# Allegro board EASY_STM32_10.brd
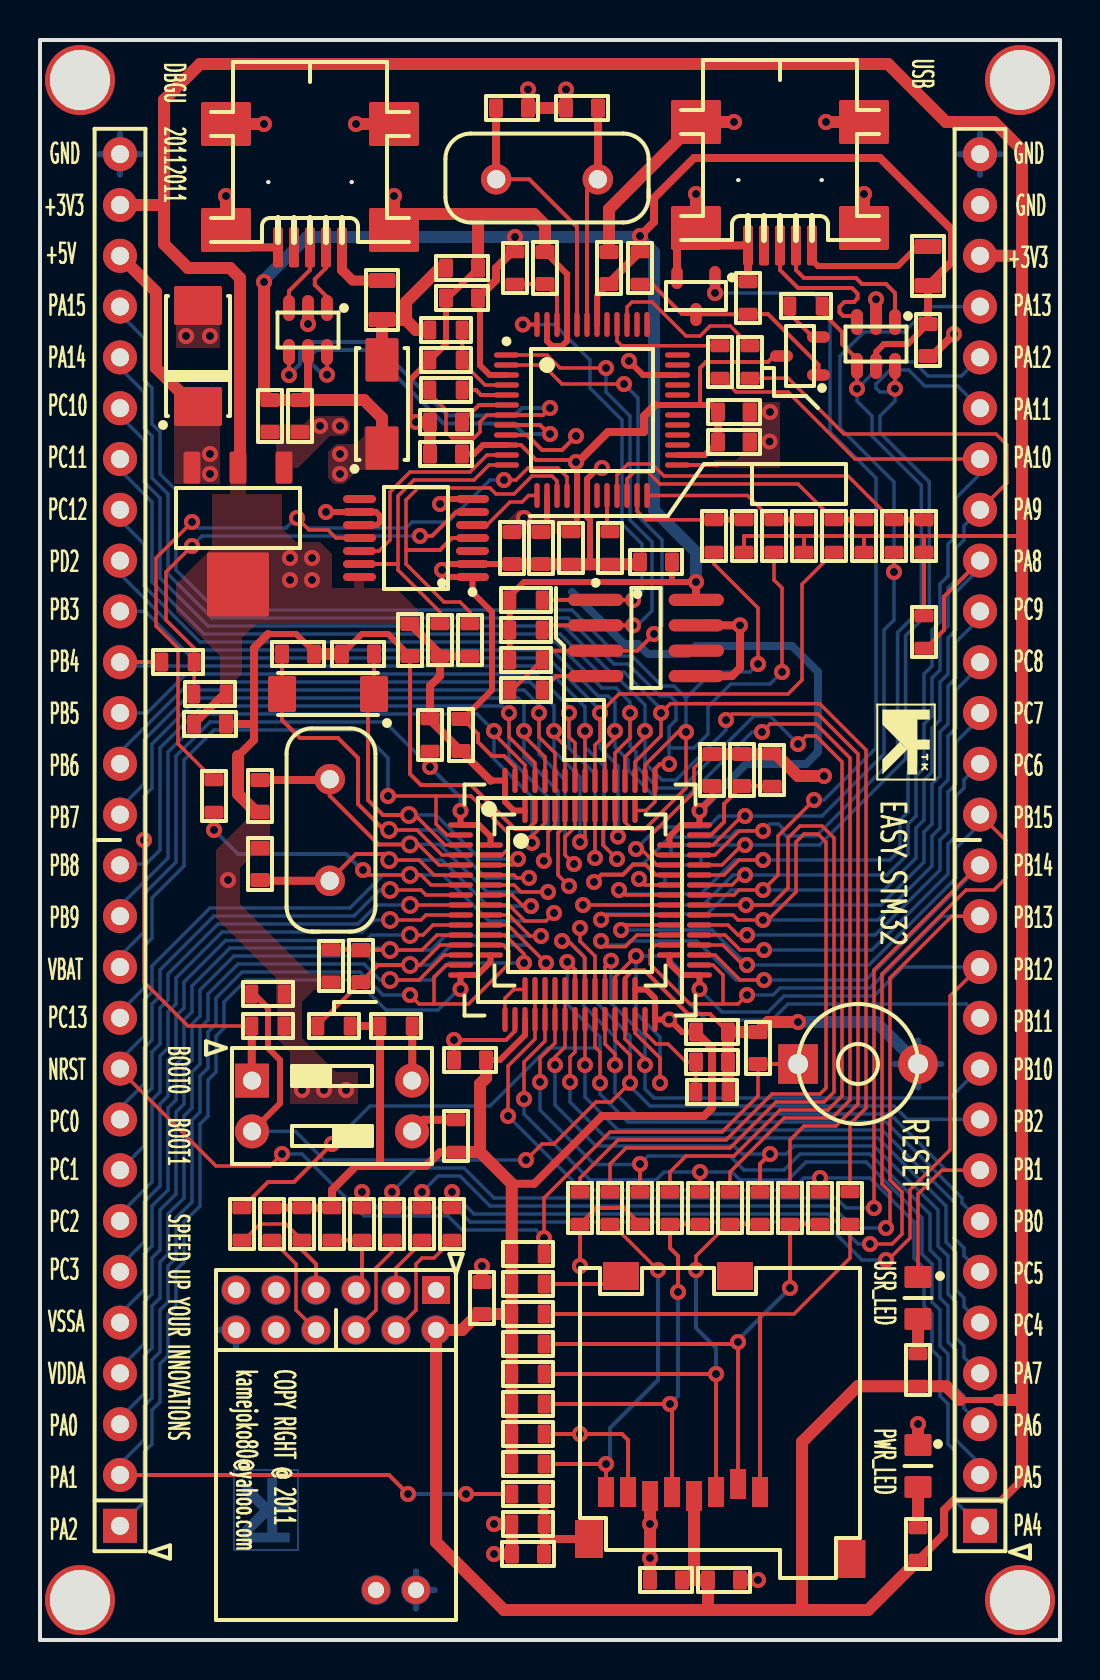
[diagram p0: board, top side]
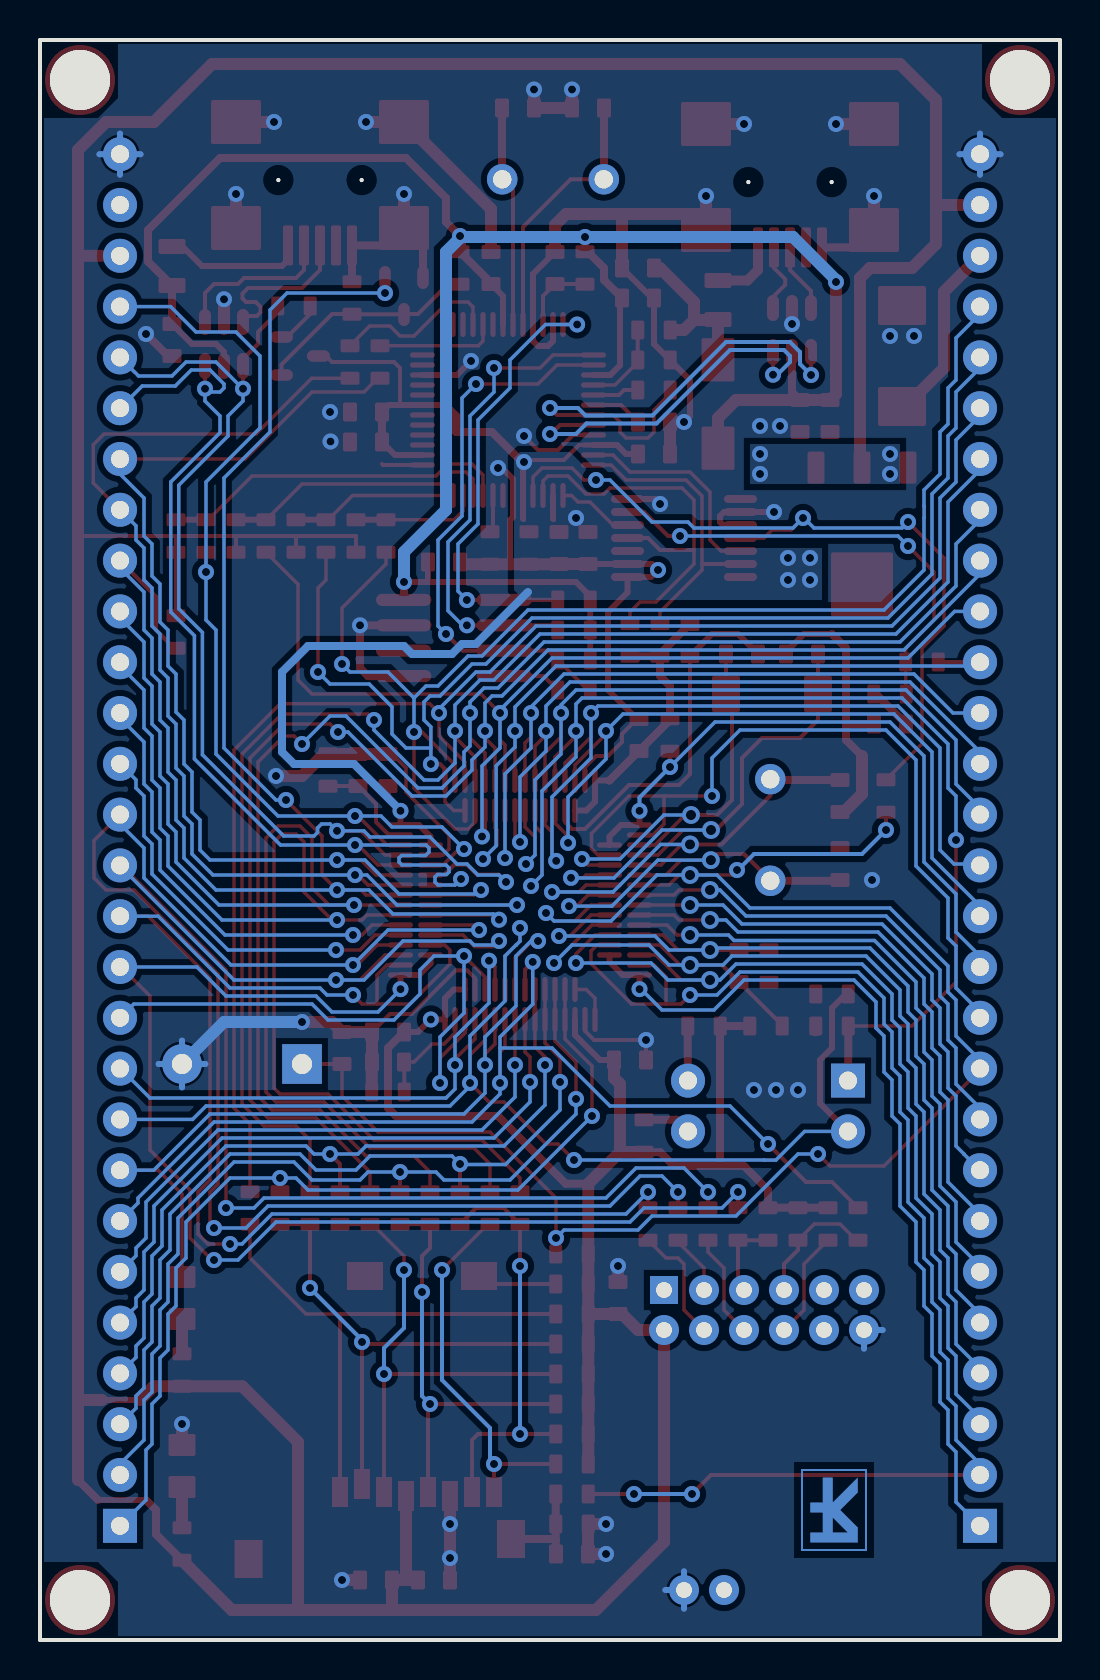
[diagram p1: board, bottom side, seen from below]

Outline 51 x 80 mm; copper layers: TOP, BOTTOM. Coordinates in mm from the lower left corner of the outline.
Outline path: 0,80 0,0 51,0 51,80 0,80

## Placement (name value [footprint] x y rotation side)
C1  22p  [CAP0603_B]  11 42.2 270 top
C2  22p  [CAP0603_B]  11 38.8 90 top
C3  15p  [CAP0603_B]  12.9 49.3 0 top
C4  15p  [CAP0603_B]  15.9 49.3 180 top
C5  100n  [CAP0603_B]  16.05 33.7 90 top
C6  100n  [CAP0603_B]  33.6 30.4 0 top
C7  100n  [CAP0603_B]  33.6 43.5 90 top
C8  100n  [CAP0603_B]  21.05 45.25 90 top
C9  100n  [CAP0603_B]  21.5 29 180 top
C10  10u  [CAP0603_B]  21.1 68.6 0 top
C11  100n  [CAP0603_B]  21.1 67.1 180 top
C12  100n  [CAP0603_B]  28.45 68.6 90 top
C13  10u  [CAP0603_B]  23.6 54.6 270 top
C14  100n  [CAP0603_B]  20.3 59.3 180 top
C15  100n  [CAP0603_B]  25.05 54.6 270 top
C16  100n  [CAP0603_B]  34.7 59.9 0 top
C17  100n  [CAP0603_B]  34.7 61.4 0 top
C18  100n  [CAP0603_B]  25.25 68.6 90 top
C19  100n  [CAP0603_B]  20.3 60.9 180 top
C20  22p  [CAP0603_B]  27.1 76.6 180 top
C21  22p  [CAP0603_B]  23.6 76.6 0 top
C22  100n  [CAP0603_B]  30.8 53.9 180 top
C23  220u  [CAP220UF]  7.9 64.2 90 top
C24  100n  [CAP0603_B]  11.5 61.2 270 top
C25  10u  [CAP0603_B]  8.5 45.8 0 top
C26  100n  [CAP0603_B]  44.4 65 270 top
C27  100n  [CAP0603_B]  33.6 28.9 0 top
C28  100n  [CAP0603_B]  35.1 43.5 90 top
C29  100n  [CAP0603_B]  13 61.2 270 top
C43  100n  [CAP0603_B]  31.3 3 180 top
C44  10u  [CAP0603_B]  34.2 3 0 top
C46  100n  [CAP0603_B]  18.5 50 270 top
C47  100n  [CAP0603_B]  24.4 4.3 180 top
C48  100n  [CAP0603_B]  35.9 29.6 90 top
C49  100n  [CAP0603_B]  22.1 17.1 90 top
D1  LED  [LEDC2012X120M]  43.9 8.7 270 top
D2  1N5819  [SS14]  17.1 61.8 90 top
D3  LED  [LEDC2012X120M]  43.9 17.1 270 top
J1  USB_MB  [HIROSE-US60-MB-5ST]  13.5 78.9 180 top
J2  USB_MB  [HIROSE-US60-MB-5ST]  37 79 180 top
J3  CON28  [CON28-1X28]  47 5.71 90 top
J4  CON28  [CON28-1X28]  4 5.71 90 top
L1  FB60R  [RES0805_B]  17.1 67 90 top
L2  FB60R  [RES0805_B]  44.4 68.7 90 top
NOREF  -  []  41.86 46.77 270 top
NOREF#2  val  [unnamed#2]  49 2 0 top
NOREF#3  -  []  0.07 0.66 0 top
NOREF#4  -  []  51.55 -0.02 90 top
NOREF#5  val  [unnamed#2]  2 78 0 top
NOREF#6  val  [unnamed#2]  49 78 0 top
NOREF#7  val  [unnamed#2]  2 2 0 top
NOREF#8  -  []  9.86 4.62 90 bottom
Q1  C1815  [SOT-23]  38 64.2 90 top
Q2  C1815  [SOT-23]  32.8 67.2 180 top
R1  0R  [RES0603_B]  19.5 45.25 90 top
R2  0R  [RES0603_B]  14.7 30.7 0 top
R3  0R  [RES0603_B]  14.55 33.7 270 top
R4  470R  [RES0603_B]  23.75 68.6 270 top
R5  4K7  [RES0603_B]  20.3 65.5 0 top
R6  10K  [RES0603_B]  20.3 64 180 top
R7  10K  [RES0603_B]  28.5 54.6 270 top
R8  10K  [RES0603_B]  24.3 49 0 top
R9  10K  [RES0603_B]  24.3 50.5 0 top
R10  10K  [RES0603_B]  24.3 52 0 top
R11  2K2  [RES0603_B]  24.3 47.5 0 top
R12  330R  [RES0603_B]  43.9 4.8 90 top
R13  1K5  [RES0603_B]  20.3 62.5 0 top
R14  100K  [RES0603_B]  26.55 54.6 270 top
R15  10K  [RES0603_B]  24.4 10.3 0 top
R16  10K  [RES0603_B]  24.4 13.3 0 top
R17  10K  [RES0603_B]  24.4 11.8 0 top
R18  10K  [RES0603_B]  24.4 14.8 0 top
R19  10K  [RES0603_B]  24.4 8.8 0 top
R20  10K  [RES0603_B]  24.4 16.3 0 top
R21  10K  [RES0603_B]  24.4 17.8 0 top
R22  1K  [RES0603_B]  24.4 5.8 180 top
R23  0R  [RES0603_B]  27 21.6 270 top
R24  0R  [RES0603_B]  34.5 21.6 270 top
R25  0R  [RES0603_B]  31.5 21.6 270 top
R26  0R  [RES0603_B]  37.5 21.6 270 top
R27  0R  [RES0603_B]  28.5 21.6 270 top
R28  0R  [RES0603_B]  40.5 21.6 270 top
R29  0R (DNP)  [RES0603_B]  30 21.6 90 top
R30  0R (DNP)  [RES0603_B]  36 21.6 90 top
R31  0R (DNP)  [RES0603_B]  33 21.6 90 top
R32  0R (DNP)  [RES0603_B]  39 21.6 90 top
R33  0R  [RES0603_B]  24.4 7.3 0 top
R34  39R  [RES0603_B]  34 63.9 270 top
R35  100R  [RES0603_B]  39.7 55.2 270 top
R36  100R  [RES0603_B]  42.7 55.2 270 top
R37  100R  [RES0603_B]  33.7 55.2 270 top
R38  100R  [RES0603_B]  36.7 55.2 270 top
R39  100K  [RES0603_B]  20 50 90 top
R40  100K  [RES0603_B]  21.5 50 90 top
R41  100R  [RES0603_B]  6.9 48.9 180 top
R42  100R  [RES0603_B]  8.7 42.2 270 top
R43  0R  [RES0603_B]  33.6 27.4 0 top
R44  10K  [RES0603_B]  30 68.6 270 top
R45  36K  [RES0603_B]  35.4 67.1 90 top
R46  1K5  [RES0603_B]  38.3 66.7 0 top
R47  47K  [RES0603_B]  44.2 50.4 270 top
R48  0R  [RES0603_B]  36.6 43.5 90 top
R49  10K  [RES0603_B]  24.4 19.3 0 top
R50  1K  [RES0603_B]  11.4 30.7 0 top
R51  1K  [RES0603_B]  11.4 32.3 0 top
R52  10K  [RES0603_B]  17.8 30.7 0 top
R53  10K  [RES0603_B]  20.8 25.2 90 top
R54  10K  [RES0603_B]  8.5 47.3 180 top
R55  10K  [RES0603_B]  41.2 55.2 90 top
R56  10K  [RES0603_B]  44.2 55.2 90 top
R57  10K  [RES0603_B]  35.2 55.2 90 top
R58  10K  [RES0603_B]  38.2 55.2 90 top
R59  39R  [RES0603_B]  35.5 63.9 270 top
R60  10K  [RES0603_B]  14.6 20.8 270 top
R61  0R  [RES0603_B]  16.1 20.8 270 top
R62  10K  [RES0603_B]  11.6 20.8 270 top
R63  10K  [RES0603_B]  13.1 20.8 270 top
R64  0R  [RES0603_B]  10.1 20.8 270 top
R65  0R  [RES0603_B]  19.1 20.8 270 top
R66  0R  [RES0603_B]  20.6 20.8 90 top
R67  0R  [RES0603_B]  17.6 20.8 90 top
R70  330R  [RES0603_B]  43.9 13.5 90 top
S1  BT  [BUTTON_RST_CIRCLE]  40.9 28.8 0 top
S2  SW DIP-2  [DIP_SWITCH_2]  14.6 26.7 270 top
U1  STM32F103RCT6  [LQFP64_MODIFIED]  27 37 0 top
U2  STM32F100  [LQFP48L_MODIFIED]  27 37 0 top
U3  FT2232D  [LQFP48L]  27.6 61.5 0 top
U4  AT93C46-10SI-2.7  [SOIC8S1JEDECM]  30.3 50.1 270 top
U6  74LVC125A  [TSOP65P640X120-14]  18.8 55.1 90 top
U7  LD1117-3V3  [SOT-223]  9.9 55.42 180 top
U8  RFM12  [RFM12-2X6]  19.8 17.5 180 top
U10  MICRO_SD  [MICRO_SD_PUSH]  41 18.6 180 top
U11  USBLC6-2P6  [SOT23-6L]  41.8 64.8 180 top
U12  USBLC6-2P6  [SOT23-6L]  13.4 65.5 180 top
Y1  8M  [XTAL_DIP]  14.49 37.96 90 top
Y2  32.768KHz  [ABS10]  14.4 47.3 180 top
Y3  6M  [XTAL_DIP]  27.89 73.04 180 top

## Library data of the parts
C1-C9 C24 C25 C27 C28 = C1005_0: User Part Number: pn; Tolerance: RichardLC
C10-C22 C26 C29 = CAP NP_0: User Part Number: pn; Tolerance: RichardLC
C23 = CAPACITOR POL: User Part Number: pn; Tolerance: RichardLC
C43 C44 C46-C49 = C1005_5: User Part Number: pn; Tolerance: RichardLC
D1 D3 = LED_0: User Part Number: pn; Tolerance: RichardLC
D2 = DIODE SCHOTTKY_1: User Part Number: pn; Tolerance: RichardLC
J1 J2 = CON9_2: User Part Number: pn; Tolerance: RichardLC
J3 J4 = CON26_0: User Part Number: pn; Tolerance: RichardLC
L1 L2 = INDUCTOR/SM_0: User Part Number: pn; Tolerance: RichardLC
NOREF#2 NOREF#6 NOREF#7 = -: User Part Number: pn; Tolerance: RichardLC
NOREF#5 = -: Tolerance: RichardLC; User Part Number: pn
Q1 Q2 = 2N3904_0: User Part Number: pn; Tolerance: RichardLC
R1-R67 R70 = R_0: User Part Number: pn; Tolerance: RichardLC
S1 = SW PUSHBUTTON_1: User Part Number: pn; Tolerance: RichardLC
S2 = SW DIP-2_1: User Part Number: pn; Tolerance: RichardLC
U1 = STM32F103RCT6_2: User Part Number: pn; Tolerance: RichardLC
U2 = STM32F100_1: User Part Number: pn; Tolerance: RichardLC
U3 = FT2232D_0: User Part Number: pn; Tolerance: RichardLC
U4 = 93C46_2: User Part Number: pn; Tolerance: RichardLC
U6 = 74HC125/LCC_0: User Part Number: pn; Tolerance: RichardLC
U7 = LD1117: User Part Number: pn; Tolerance: RichardLC
U8 = RFM12: User Part Number: pn; Tolerance: RichardLC
U10 = MOLEX_uSD_0: User Part Number: pn; Tolerance: RichardLC
U11 U12 = USBLC6-2P6: User Part Number: pn; Tolerance: RichardLC
Y1 Y3 = ZTB: Tolerance: ***; User Part Number: ***
Y2 = ZTA: User Part Number: pn; Tolerance: RichardLC

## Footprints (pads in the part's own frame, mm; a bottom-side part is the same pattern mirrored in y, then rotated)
ABS10
  custom 0.35x0.35 smd: 1(-2.3,0) 2(2.3,0)
BUTTON_RST_CIRCLE
  rect 1.98x1.98 hole 1: 1(-3,0)
  round 1.98 hole 1: 2(3,0)
CAP220UF
  custom 0.487x0.487 smd: 1(-2.525,0) 2(2.525,0)
CAP0603_B
  custom 0.175x0.175 smd: 1(-0.8,0) 2(0.8,0)
CON28-1X28
  rect 1.7x1.7 hole 0.9: 1(0,0)
  round 1.7 hole 0.9: 2(2.54,0) 3(5.08,0) 4(7.62,0) 5(10.16,0) 6(12.7,0) 7(15.24,0) 8(17.78,0) 9(20.32,0) 10(22.86,0) 11(25.4,0) 12(27.94,0) 13(30.48,0) 14(33.02,0) 15(35.56,0) 16(38.1,0) 17(40.64,0) 18(43.18,0) 19(45.72,0) 20(48.26,0) 21(50.8,0) 22(53.34,0) 23(55.88,0) 24(58.42,0) 25(60.96,0) 26(63.5,0) 27(66.04,0) 28(68.58,0)
DIP_SWITCH_2
  rect 1.7x1.7 hole 0.9: 1(-1.27,-4)
  round 1.7 hole 0.9: 2(1.27,-4) 3(1.27,4) 4(-1.27,4)
HIROSE-US60-MB-5ST
  round 0.2 hole 0.9 unplated: (-2.083,6.005) (2.083,6.005)
  custom 0.125x0.125 smd: 1(-1.6,9.271) 2(-0.8,9.271) 3(0,9.271) 4(0.8,9.271) 5(1.6,9.271)
  custom 0.55x0.55 smd: 6(-4.2,3.1) 7(4.2,3.1) 8(-4.2,8.4) 9(4.2,8.4)
LEDC2012X120M
  custom 0.275x0.275 smd: A(1.05,0) C(-1.05,0)
LQFP48L
  oval 1.25x0.27 smd: 1(-4.275,2.75) 2(-4.275,2.25) 3(-4.275,1.75) 4(-4.275,1.25) 5(-4.275,0.75) 6(-4.275,0.25) 7(-4.275,-0.25) 8(-4.275,-0.75) 9(-4.275,-1.25) 10(-4.275,-1.75) 11(-4.275,-2.25) 12(-4.275,-2.75) 25(4.275,-2.75) 26(4.275,-2.25) 27(4.275,-1.75) 28(4.275,-1.25) 29(4.275,-0.75) 30(4.275,-0.25) 31(4.275,0.25) 32(4.275,0.75) 33(4.275,1.25) 34(4.275,1.75) 35(4.275,2.25) 36(4.275,2.75)
  oval 0.27x1.25 smd: 13(-2.75,-4.275) 14(-2.25,-4.275) 15(-1.75,-4.275) 16(-1.25,-4.275) 17(-0.75,-4.275) 18(-0.25,-4.275) 19(0.25,-4.275) 20(0.75,-4.275) 21(1.25,-4.275) 22(1.75,-4.275) 23(2.25,-4.275) 24(2.75,-4.275) 37(2.75,4.275) 38(2.25,4.275) 39(1.75,4.275) 40(1.25,4.275) 41(0.75,4.275) 42(0.25,4.275) 43(-0.25,4.275) 44(-0.75,4.275) 45(-1.25,4.275) 46(-1.75,4.275) 47(-2.25,4.275) 48(-2.75,4.275)
LQFP48L_MODIFIED
  oval 1.25x0.27 smd: 1(-4.475,2.75) 2(-4.475,2.25) 3(-4.475,1.75) 4(-4.475,1.25) 5(-4.475,0.75) 6(-4.475,0.25) 7(-4.475,-0.25) 8(-4.475,-0.75) 9(-4.475,-1.25) 10(-4.475,-1.75) 11(-4.475,-2.25) 12(-4.475,-2.75) 25(4.475,-2.75) 26(4.475,-2.25) 27(4.475,-1.75) 28(4.475,-1.25) 29(4.475,-0.75) 30(4.475,-0.25) 31(4.475,0.25) 32(4.475,0.75) 33(4.475,1.25) 34(4.475,1.75) 35(4.475,2.25) 36(4.475,2.75)
  oval 0.27x1.25 smd: 13(-2.75,-4.475) 14(-2.25,-4.475) 15(-1.75,-4.475) 16(-1.25,-4.475) 17(-0.75,-4.475) 18(-0.25,-4.475) 19(0.25,-4.475) 20(0.75,-4.475) 21(1.25,-4.475) 22(1.75,-4.475) 23(2.25,-4.475) 24(2.75,-4.475) 37(2.75,4.475) 38(2.25,4.475) 39(1.75,4.475) 40(1.25,4.475) 41(0.75,4.475) 42(0.25,4.475) 43(-0.25,4.475) 44(-0.75,4.475) 45(-1.25,4.475) 46(-1.75,4.475) 47(-2.25,4.475) 48(-2.75,4.475)
LQFP64_MODIFIED
  oval 1.25x0.27 smd: 1(-5.975,3.75) 2(-5.975,3.25) 3(-5.975,2.75) 4(-5.975,2.25) 5(-5.975,1.75) 6(-5.975,1.25) 7(-5.975,0.75) 8(-5.975,0.25) 9(-5.975,-0.25) 10(-5.975,-0.75) 11(-5.975,-1.25) 12(-5.975,-1.75) 13(-5.975,-2.25) 14(-5.975,-2.75) 15(-5.975,-3.25) 16(-5.975,-3.75) 33(5.975,-3.75) 34(5.975,-3.25) 35(5.975,-2.75) 36(5.975,-2.25) 37(5.975,-1.75) 38(5.975,-1.25) 39(5.975,-0.75) 40(5.975,-0.25) 41(5.975,0.25) 42(5.975,0.75) 43(5.975,1.25) 44(5.975,1.75) 45(5.975,2.25) 46(5.975,2.75) 47(5.975,3.25) 48(5.975,3.75)
  oval 0.27x1.25 smd: 17(-3.75,-5.975) 18(-3.25,-5.975) 19(-2.75,-5.975) 20(-2.25,-5.975) 21(-1.75,-5.975) 22(-1.25,-5.975) 23(-0.75,-5.975) 24(-0.25,-5.975) 25(0.25,-5.975) 26(0.75,-5.975) 27(1.25,-5.975) 28(1.75,-5.975) 29(2.25,-5.975) 30(2.75,-5.975) 31(3.25,-5.975) 32(3.75,-5.975) 49(3.75,5.975) 50(3.25,5.975) 51(2.75,5.975) 52(2.25,5.975) 53(1.75,5.975) 54(1.25,5.975) 55(0.75,5.975) 56(0.25,5.975) 57(-0.25,5.975) 58(-0.75,5.975) 59(-1.25,5.975) 60(-1.75,5.975) 61(-2.25,5.975) 62(-2.75,5.975) 63(-3.25,5.975) 64(-3.75,5.975)
MICRO_SD_PUSH
  rect 0.8x1.5 smd: 1(5,11.2) 2(6.1,10.8) 3(7.2,11.2) 4(8.3,11.4) 5(9.4,11.2) 6(10.5,11.4) 7(11.6,11.2) 8(12.7,11.2)
  rect 1.4x1.9 smd: G1(0.43,14.55) G2(13.55,13.55)
  rect 1.8x1.4 smd: S1(6.25,0.4) S2(11.95,0.4)
RES0603_B
  custom 0.163x0.163 smd: 1(-0.812,0) 2(0.812,0)
RES0805_B
  custom 0.188x0.188 smd: 1(-0.975,0) 2(0.975,0)
RFM12-2X6
  rect 1.4x1.4 hole 0.8: 1(0,0)
  round 1.4 hole 0.8: 2(0,2) 3(2,0) 4(2,2) 5(4,0) 6(4,2) 7(6,0) 8(6,2) 9(8,0) 10(8,2) 11(10,0) 12(10,2) 13(1,15) 14(3,15)
SOIC8S1JEDECM
  oval 0.61x2.77 smd: 1(-1.905,-2.515) 2(-0.635,-2.515) 3(0.635,-2.515) 4(1.905,-2.515) 5(1.905,2.515) 6(0.635,2.515) 7(-0.635,2.515) 8(-1.905,2.515)
SOT23-6L
  oval 0.6x1.3 smd: 1(-0.95,-1.1) 2(0,-1.1) 3(0.95,-1.1) 4(0.95,1.1) 5(0,1.1) 6(-0.95,1.1)
SOT-23
  oval 0.58x1.15 smd: 1(-0.95,-0.925) 2(0.95,-0.925) 3(0,0.925)
SOT-223
  custom 0.21x0.21 smd: 1(-2.3,-3.195) 2(0,-3.195) 3(2.3,-3.195)
  custom 0.775x0.775 smd: 4(0,2.645)
SS14
  custom 0.412x0.412 smd: A(2.21,0) C(-2.21,0)
TSOP65P640X120-14
  oval 0.4x1.65 smd: 1(-1.95,-2.825) 2(-1.3,-2.825) 3(-0.65,-2.825) 4(0,-2.825) 5(0.65,-2.825) 6(1.3,-2.825) 7(1.95,-2.825) 8(1.95,2.825) 9(1.3,2.825) 10(0.65,2.825) 11(0,2.825) 12(-0.65,2.825) 13(-1.3,2.825) 14(-1.95,2.825)
unnamed#2
  round 3.5 hole 3: 1(0,0)
XTAL_DIP
  round 1.524 hole 0.914: 1(0,0) 2(5.08,0)

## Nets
+3V3: C6.1 C7.1 C8.1 C9.1 C13.1 C14.1 C15.1 C16.1 C17.1 C25.1 C43.1 C44.1 C46.1 C49.1 J3.26 J4.27 Q1.3(C) R1.2 R2.2 R12.1 R14.1 R15.1 R16.1 R17.1 R18.1 R19.1 R20.1 R21.1 R39.1 R40.1 R47.1 R49.1 R52.1 R53.1 R54.1 R55.1 R56.1 R57.1 R58.1 R60.1 R62.1 R63.1 R70.1 U1.19(VDD_4) U1.32(VDD_1) U1.48(VDD_2) U1.64(VDD_3) U2.24(VDD_1) U2.36(VDD_2) U2.48(VDD_3) U3.10(SI/WUA) U3.14(VCCIOA) U3.17(ADBUS6) U3.26(SI/WUB) U3.31(VCCIOB) U6.14(VCC) U7.2(VOUT) U7.4(SH) U8.2(VDD) U10.4(VDD)
+5V: C11.1 C12.1 C22.1 C23.1 C24.1 C26.1 C29.1 D2.C J4.26 L2.1 R4.1 R8.1 R9.1 R10.1 R44.1 U3.3(VCC1) U3.42(VCC2) U4.8(VCC) U7.3(VIN) U11.5(VBUS) U12.5(VBUS)
GND: C1.2 C2.2 C3.2 C4.2 C6.2 C7.2 C8.2 C9.2 C10.2 C11.2 C12.2 C13.2 C14.2 C15.2 C16.2 C17.2 C18.2 C19.2 C20.2 C21.2 C22.2 C23.2 C24.2 C25.2 C26.2 C27.2 C28.2 C29.2 C43.2 C44.2 C46.2 C47.2 C48.2 C49.2 D1.C J1.5(GND) J1.6(SH1) J1.7(SH2) J1.8(SH3) J1.9(SH4) J2.5(GND) J2.6(SH1) J2.7(SH2) J2.8(SH3) J2.9(SH4) J3.28 J4.28 Q2.2(E) R3.2 R6.2 R7.2 R14.2 R22.2 R43.2 R45.2 R48.2 R50.2 R51.2 S1.2 U1.18(VSS_4) U1.63(VSS_3) U2.23(VSS_1) U2.35(VSS_2) U2.47(VSS_3) U3.9(GND1) U3.18(GND2) U3.25(GND3) U3.34(GND4) U3.45(AGND) U3.47(TEST) U4.5(GND) U4.7(NC) U6.1(O\E\1\) U6.2(A1) U6.7(GND) U6.9(A3) U6.10(O\E\3\) U7.1(GND) U8.12(GND1) U8.13(GND2) U10.6(VSS) U11.2(GND) U12.2(GND)
VBAT: J4.12 R1.1 U1.1(VBAT) U2.1(VBAT)
VDDA: C5.1 J4.4 R2.1 U1.13(VDDA) U2.9(VDDA)
VSSA: C5.2 J4.5 R3.1 U1.12(VSSA) U2.8(VSSA)
BOOT0: R50.1 S2.1 U1.60(BOOT0) U2.44(BOOT0)
EECK: R9.2 U3.1(EESK) U4.2(CLK)
EECS: R10.2 U3.48(EECS) U4.1(CS)
EEDA: R8.2 R11.1 U3.2(EEDATA) U4.3(DI)
JT_SRSTN: R42.1 U3.16(ADBUS7) U6.11(Y4)
JTAG_SELN: J3.27
NRST: C48.1 J4.10 R42.2 R49.2 S1.1 U1.7(NRST) U2.7(NRST)
OSC32_IN: C4.1 U1.3(PC14/OSC32_IN) U2.3(PC14/OSC32_IN) Y2.1
OSC32_OUT: C3.1 U1.4(PC15/OSC32/OUT) U2.4(PC15/OSC32_OUT) Y2.2
OSC_IN: C1.1 U1.5(PD0/OSC_IN) U2.5(PD0/OSC_IN) Y1.2
OSC_OUT: C2.1 U1.6(PD1/OSC_OUT) U2.6(PD1/OSC_OUT) Y1.1
PA0: J4.3 U1.14(PA0-WKUP) U2.10(PA0/WKUP)
PA1: J4.2 R33.1 U1.15(PA1) U2.11(PA1)
PA2: J4.1 U1.16(PA2) U2.12(PA2)
PA3: U1.17(PA3) U2.13(PA3)
PA4: J3.1 R32.2 U1.20(PA4) U2.14(PA4)
PA5: J3.2 R31.2 U1.21(PA5) U2.15(PA5)
PA6: J3.3 R29.2 U1.22(PA6) U2.16(PA6)
PA7: J3.4 R30.2 U1.23(PA7) U2.17(PA7)
PA8: J3.20 Q2.1(B) R47.2 U1.41(PA8) U2.29(PA8)
PA9: J3.21 R59.2 U1.42(PA9) U2.30(PA9)
PA10: J3.22 R34.2 U1.43(PA10) U2.31(PA10)
PA11: J3.23 U1.44(PA11) U2.32(PA11) U11.6(IO1_2)
PA12: J3.24 R46.2 U1.45(PA12) U2.33(PA12) U11.4(IO2_2)
PA13: J3.25 R36.2 U1.46(PA13) U2.34(PA13)
PA14: J4.24 R38.2 U1.49(PA14) U2.37(PA14)
PA15: J4.25 R37.2 U1.50(PA15) U2.38(PA15)
PB0: J3.7 R64.1 U1.26(PB0) U2.18(PB0)
PB1: D3.C J3.8 U1.27(PB1) U2.19(PB1)
PB2: J3.9 R51.1 S2.2 U1.28(PB2/BOOT1) U2.20(PB2)
PB3: J4.19 R35.2 U1.55(PB3) U2.39(PB3)
PB4: J4.18 R41.2 U1.56(PB4) U2.40(PB4)
PB5: J4.17 U1.57(PB5) U2.41(PB5)
PB6: J4.16 U1.58(PB6) U2.42(PB6)
PB7: J4.15 U1.59(PB7) U2.43(PB7)
PB8: J4.14 U1.61(PB8) U2.45(PB8)
PB9: J4.13 U1.62(PB9) U2.46(PB9)
PB10: J3.10 U1.29(PB10) U2.21(PB10)
PB11: J3.11 U1.30(PB11) U2.22(PB11)
PB12: J3.12 R61.1 U1.33(PB12) U2.25(PB12)
PB13: J3.13 R66.2 U1.34(PB13) U2.26(PB13)
PB14: J3.14 R67.2 U1.35(PB14) U2.27(PB14)
PB15: J3.15 R65.1 U1.36(PB15) U2.28(PB15)
PC0: J4.9 U1.8(PC0)
PC1: J4.8 U1.9(PC1)
PC2: J4.7 U1.10(PC2)
PC3: J4.6 U1.11(PC3)
PC4: J3.5 U1.24(PC4)
PC5: J3.6 U1.25(PC5)
PC6: J3.16 U1.37(PC6)
PC7: J3.17 U1.38(PC7)
PC8: J3.18 R23.1 U1.39(PC8)
PC9: J3.19 R27.1 U1.40(PC9)
PC10: J4.23 R28.1 U1.51(PC10)
PC11: J4.22 R26.1 U1.52(PC11)
PC12: J4.21 R25.1 U1.53(PC12)
PC13: J4.11 U1.2(PC13/TAMPER/RTC) U2.2(PC13/TAMPER/RTC)
PD2: J4.20 R24.1 U1.54(PD2)
RXD: R59.1 U3.39(BDBUS1)
SRST: U3.11(ACBUS3) U6.12(A4)
SRST_OE: R39.2 U3.12(ACBUS2) U6.13(O\E\4\)
TRST: U3.13(ACBUS1) U6.5(A2)
TRST_OE: R40.2 U3.15(ACBUS0) U6.4(O\E\2\)
TXD: R34.1 U3.40(BDBUS0)
USB_CLK: R38.1 R58.2 U3.24(ADBUS0)
USB_TDI: R37.1 R57.2 U3.23(ADBUS1)
USB_TDO: R35.1 R55.2 U3.22(ADBUS2)
USB_TMS: R36.1 R56.2 U3.21(ADBUS3)
N50123: R13.1 U3.7(USBDP) U12.4(IO2_2)
N50127: C18.1 R4.2 U3.46(AVCC)
N50535: R7.1 U3.20(ADBUS4)
N50793: C20.1 U3.43(XTIN) Y3.1
N50801: C21.1 U3.44(XTOUT) Y3.2
N51029: C10.1 D2.A L1.1 R5.1
N51243: J1.1(VBUS) L1.2
N51319: R13.2 U3.5(R\S\T\O\U\T\)
N51343: U3.8(USBDM) U12.6(IO1_2)
N51347: R5.2 R6.1 U3.4(R\E\S\E\T\)
N51363: C19.1 U3.6(3V3OUT)
N51511: R11.2 U4.4(DO)
N51727: D1.A R12.2
N70187: R15.2 R23.2 R29.1 U10.7(DAT0/DO)
N70219: R17.2 R25.2 R31.1 U10.5(CLK)
N70227: R18.2 R26.2 R32.1 U10.2(CD/C\S\/DAT3)
N70305: R21.2 U10.S2
N70345: C47.1 R22.1 R33.2 U10.G2
N70603: R19.2 R27.2 U10.8(DAT1/RSV)
N14914218: R16.2 R24.2 R30.1 U10.3(CMD/DI)
N14919761: R20.2 R28.2 U10.1(DAT2/NC)
N14928576: R41.1 R54.2 U6.6(Y2)
N14948550: J2.1(VBUS) L2.2
N14948554: J2.2(DM) U11.1(IO1_1)
N14948558: J2.3(DP) U11.3(IO2_1)
N14952468: Q1.2(E) R46.1
N14953185: Q1.1(B) Q2.3(C) R44.2 R45.1
N14959571: J1.3(DP) U12.3(IO2_1)
N14961045: J1.2(DM) U12.1(IO1_1)
N14964930: C27.1 R43.1 U1.31(VSS_1)
N14964937: C28.1 R48.1 U1.47(VSS_2)
N14983071: R52.2 S2.4
N14983075: R53.2 S2.3
N14990127: R62.2 U8.8(FSK/DATA/NFFS)
N14990147: R66.1 U8.4(SCK)
N14990153: R67.1 U8.6(SDO)
N14990191: R65.2 U8.3(SDI)
N14990197: R60.2 R61.2 U8.5(NSEL)
N14990201: R63.2 R64.2 U8.7(NIR0)
N15001570: D3.A R70.2

Pads without a net: J1 4; J2 4; NOREF#2 1; NOREF#5 1; NOREF#6 1; NOREF#7 1; U3 19 27 28 29 30 32 33 35 36 37 38 41; U4 6; U6 3 8; U8 1 9 10 11 14; U10 G1 S1

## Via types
v1: diameter 0.8, hole 0.4, TOP to BOTTOM, 186 vias
v2: diameter 0.889, hole 0.508, TOP to BOTTOM, 12 vias

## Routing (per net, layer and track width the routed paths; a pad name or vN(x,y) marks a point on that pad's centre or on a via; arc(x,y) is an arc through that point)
+3V3: length 375.2
  TOP w0.2: R55.1 41.2,55.2 ; 41.2,55.2 38.2,55.2 ; 41.2,55.2 44.2,55.2 ; 38.2,55.2 35.2,55.2 R57.1 ; 38.2,55.2 R58.1 ; 44.2,55.2 49.1,55.2 ; 44.2,55.2 R56.1 R47.1 ; 49.09,69.21 49.1,69.2 ; 26.8,56 26.85,56.05 ; v1(26.8,58.9) 26.7,59 24.8,59 24.05,59.75 U3.10 ; 33,61.75 33,63.6 33.3,63.9 36.4,63.9 36.7,64.2 Q1.3 ; 25.3,56 25.35,56.05
  TOP w0.3: 25.35,56.05 U3.14 ; U2.24 30.32,32.52 30.57,32.27 30.75,32.09 U1.32 v1(31.46,31.02) 31.48,31.02 32.1,30.4 C6.1 ; C14.1 21.7,59.3 22.15,59.75 U3.10 ; C9.1 23,29 24.25,30.25 U1.19 ; 30.75,61.75 U3.31 33.55,61.75 C17.1 ; 26.9,58.9 v1(26.8,58.9) 26.85,58.85 U3.17 26.85,56.05 ; U3.26 33.25,59.25 C16.1 ; 48.1,7 45.7,7 ; U2.48 23.69,41.48 23.25,41.91 U1.64 22.54,42.98 ; C7.1 33.6,42.1 32.98,41.48 v1(32.98,41.46) U1.48 32.05,40.75 31.48,40.17 U2.36 ; 46,12 47.9,12
  TOP w0.4: 45.7,7 45.2,6.5 45.2,5.29 R12.1 ; 26.9,58.9 28.4,60.4 30.2,60.4 30.2,61.2 30.75,61.75 ; 17,23.7 17,30.69 R52.1 R2.2 ; 17,23.7 15.8,23.7 14.6,22.5 R60.1 R63.1 R62.1 ; 17,23.7 19.3,23.7 19.99,24.39 R53.1 ; 22.54,42.98 22.52,42.98 C8.1 19.5,46 R1.2 19.5,47.7 20,48.2 R39.1 ; R39.1 20,49.3 C46.1 ; R39.1 R40.1 ; 23.59,22.81 24.71,22.81 28.1,26.2 33.2,26.2 33.6,26.6 33.6,29.6 C6.1 ; 49.1,8 48.1,7 ; C16.1 C17.1 ; C25.1 9.2,47.3 R54.1
  TOP w0.6: R12.1 41.41,1.5 38.1,1.5 ; 22,24.4 20.81,24.4 R53.1 ; 22,24.4 22,27.8 22.3,28.1 C9.1 ; 22,24.4 23.59,22.81 R49.1 R21.1 R20.1 ; 38.1,1.5 38.1,9.9 40.89,12.69 R70.1 45.31,12.69 46,12 ; 38.1,1.5 33.4,1.5 ; J3.26 49.09,69.21 ; R20.1 C49.1 21.9,16.3 21.1,15.5 U8.2 19.8,4.9 23.2,1.5 33.4,1.5 ; R20.1 R18.1 R16.1 R17.1 R15.1 R19.1 ; 32.7,3 U10.4 ; 32.7,3 C43.1 ; 32.7,3 C44.1 33.4,1.5 ; 47.9,12 49.1,12 ; 49.1,12 49.1,8 ; 49.1,12 49.1,74.5 47.7,75.9 45.3,75.9 42.4,78.8 8,78.8 6.2,77 6.2,71.7 ; 6.2,71.7 6.15,71.75 J4.27 ; 6.2,71.7 6.2,69.8 7.4,68.6 9.5,68.6 10,68.1 10,58.72 U7.2
  BOTTOM w0.4: 26.6,52.4 29.2,49.8 29.9,49.8 30.4,49.3 32.4,49.3 32.8,49.7 37.6,49.7 38.9,48.4 38.9,44.4 38.3,43.8 35.3,43.8 32.98,41.48 v1(32.98,41.46)
  vias: v1(12.5,54.1) v1(12.5,53) v1(13.6,54.1) v1(13.6,53) v1(24.2,56.1)
+5V: length 120.9
  TOP w0.2: C23.1 7.73,61.67
  TOP w0.3: C12.1 27.85,67.2 U3.42 ; C26.1 43.4,64.8 42.2,64.8 41.8,64.4 U11.5 ; U3.3 22.48,63.25 22,63.73 22,67 C11.1 ; R8.1 R9.1 R10.1 23.49,52.19 24.2,52.9 31.6,52.9 ; C22.1 31.6,52.9 ; 31.6,52.9 v1(32.8,52.9)
  TOP w0.4: v1(23.75,70.15) R4.1 23.61,69.41 22.8,68.6 22.8,68 C11.1 ; R44.1 28.45,67.86 C12.1 ; 32.81,52.01 32.8,52.02 v1(32.8,52.9) ; C26.1 L2.1 45.6,68.92 45.6,70.5 42,74.1 32.7,74.1 30.7,72.1 30.7,70.9 v1(30,70.2) ; U12.5 13.4,62.4 C29.1
  TOP w0.6: D2.C 17.1,61.1 16.2,62 C29.1 C24.1 11.2,62.3 v1(11.2,67.9) ; 7.73,61.67 5.8,63.6 5.8,67.41 J4.26 ; R44.1 v1(30,70.2)
  BOTTOM w0.2: 29.95,70.15 v1(30,70.2)
  BOTTOM w0.6: v1(11.2,67.9) 11.2,68 13.35,70.15 v1(23.75,70.15) 29.95,70.15 30.7,69.4 30.7,56.5 32.8,54.4 v1(32.8,52.9)
  vias: v1(8.5,59.3) v1(8.5,58.3) v1(15,59.3) v1(15,58.3)
GND: length 223.4
  TOP w0.175: C7.2 33.4,44.3 32.7,43.6 32.7,42.4 30.55,40.25 30.55,39.55 30.85,39.25 U2.35
  TOP w0.2: C9.2 v1(20.7,30) 23.3,30 23.75,30.45 U1.18 ; 23.6,5.79 R22.2 ; C6.2 33.5,31.3 32.4,31.3 30.22,33.48 29.63,33.48 29.25,33.09 U2.23 ; U1.63 23.75,43.65 23.2,44.2 22.6,44.2 21.9,44.9 21.9,45.3 21.15,46.05 C8.2 ; C46.2 18.5,43.3 19.05,42.75 21.55,42.75 23.75,40.55 24.4,40.55 24.75,40.9 U2.47 ; v1(26.8,60.2) 26.1,59.5 25.1,59.5 24.35,60.25 U3.9 ; 33.9,58.8 33.85,58.75 U3.25
  TOP w0.3: v1(20,56.8) 20.25,57.05 21.62,57.05 ; C10.2 20.4,67.1 C11.2 20.3,64.8 19.5,64 R6.2 19.49,63.99 18.5,63 18.5,61.2 v1(18.8,60.9) ; C13.2 20.4,53.8 v1(20.1,53.5) 20.45,53.15 21.62,53.15 21.62,52.38 22.6,51.4 22.6,47.5 21.15,46.05 ; C46.2 17.4,50.3 16.1,50.3 C4.2 ; 27.5,53.79 27.5,56 27.35,56.15 U3.18 27.35,58.05 27.9,58.6 v1(28.1,58.6) ; 11.4,50.3 12.8,50.3 13.7,49.4 C3.2 ; U3.34 30.15,63.25 v1(29.45,63.95) ; C18.2 26.35,68.3 U3.45 26.35,64.95 26.1,64.7 25.6,64.7 25.35,64.95 U3.47 ; U6.10 16.85,55.75 17,55.9 17,56.2 16.8,56.4 U6.9 v1(14.3,56.4)
  TOP w0.4: R45.2 J2.5 33.67,69.73 J2.9 31.85,69.65 Q2.2 ; 11.4,50.3 10.7,49.6 10.7,45.8 ; J1.5 10.17,69.63 J1.9 ; C25.2 10.7,45.8 ; 10.7,45.8 10.7,45 9.9,44.2 ; v1(45.7,65.3) 44.6,64.2 C26.2 ; 32.81,48.2 34.59,48.2 35,48.6 v1(35,50.73) 32.81,50.73
  TOP w0.6: U11.2 v1(41.8,67.04) ; C1.2 10.8,41.4 9.9,42.3 9.9,44.2 ; J2.8 v1(41.2,72.3) ; 21.9,71.3 18.5,71.3 J1.8 v1(17.7,72.2) ; 21.9,71.3 24.7,71.3 25.25,70.75 C18.2 ; 21.9,71.3 C10.2 ; v1(39.2,43.2) 37.9,43.2 36.79,44.31 R48.2 36.59,44.3 C28.2 C7.2 ; R43.2 34.41,28.89 C27.2 C6.2 C48.2 36.4,30.9 v1(37.9,30.9) ; C3.2 C4.2 ; v1(26.3,77.53) C20.2 C21.2 v1(24.4,77.53) ; C14.2 C19.2 v1(18.8,60.9) ; C12.2 28.45,71.55 J2.7 v1(34.7,75.9) ; R22.2 v1(22.7,5.8) ; U12.2 v1(13.4,65.8) ; C49.2 v1(22.1,18.7) ; J2.9 v1(32.8,72.3) ; U10.6 v1(30.5,5.8) v1(30.5,4.1) C43.2 ; 23.6,5.79 C47.2 v1(22.7,4.3) ; D1.C v1(43.9,10.8) ; 12.21,30.49 R50.2 ; J2.6 v1(39.3,75.9) ; J1.6 v1(15.8,75.8) ; J1.9 v1(9.3,72.2) ; J1.7 v1(11.2,75.8) ; C13.2 C15.2 25.06,53.79 R14.2 R7.2 29.89,53.79 C22.2 ; C44.2 v1(35.9,3)
  BOTTOM w0.305: S1.2 43.9,29.97 ; S1.2 42.73,28.8 ; S1.2 45.07,28.8 ; S1.2 43.9,27.63 ; 9.8,14.57 U8.12 8.87,15.5 ; 45.97,74.29 J3.28 ; J3.28 47,75.32 ; J3.28 47,73.26 ; J3.28 48.03,74.29 ; 4,73.26 J4.28 ; J4.28 4,75.32 ; J4.28 5.03,74.29 ; J4.28 2.97,74.29 ; 18.8,1.57 U8.13 ; U8.13 18.8,3.43 ; U8.13 19.73,2.5
  BOTTOM w0.6: v1(37.9,30.9) 41.8,30.9 S1.2
  vias: v1(7.3,65.2) v1(8.5,65.2) v1(9.4,38) v1(13.1,27.5) v1(14,60.7) v1(14.2,27.5) v1(15,60.7) v1(15.3,27.5) v1(36.5,61.4) v1(36.48,59.92)
VBAT: length 32.5
  TOP w0.2: R1.1 v1(19.5,43.65)
  TOP w0.3: U2.1 22.52,40.17 21.95,40.75 U1.1 v1(21.02,41.46)
  BOTTOM w0.175: v1(19.5,43.65) 17.25,45.9 8.5,45.9 6.8,44.2 6.8,38.9 5.2,37.3 5.2,35.4 4,34.2 J4.12
  BOTTOM w0.2: v1(19.5,43.65) 21.02,42.12 v1(21.02,41.46)
VDDA: length 52.2
  TOP w0.175: U2.9 23.4,35.75 v1(25.3,33.85) ; v2(18.5,33.75) 19,33.75 20,34.75 U1.13
  TOP w0.2: R2.1 13.89,30.74 C5.1 16.9,33.75 v2(18.5,33.75)
  BOTTOM w0.175: J4.4 4,13.6 5.2,14.8 5.2,16.9 5.6,17.3 5.6,19.1 6,19.5 6,21.5 6.8,22.3 6.8,26.4 7.2,26.8 7.2,28.6 7.6,29 7.6,30.8 8,31.2 8,32.5 9.7,34.2 16.4,34.2 16.85,33.75 v2(18.5,33.75) 19.55,33.75 20.55,34.75 24.4,34.75 v1(25.3,33.85)
VSSA: length 46.6
  TOP w0.175: U2.8 23.45,36.25 24.5,35.2 v1(25.05,35.2) ; v2(17.5,34.5) 19.1,34.5 19.85,35.25 U1.12
  TOP w0.2: v2(17.5,34.5) C5.2 16.04,34.51 R3.1
  BOTTOM w0.175: v1(25.05,35.2) 20.25,35.2 19.55,34.5 v2(17.5,34.5) 17.4,34.6 9.5,34.6 7.6,32.7 7.6,31.4 7.2,31 7.2,29.2 6.8,28.8 6.8,27 6.4,26.6 6.4,22.5 5.6,21.7 5.6,19.7 5.2,19.3 5.2,17.5 4,16.3 J4.5
BOOT0: length 57.9
  TOP w0.175: U2.44 26.25,40.7 25.9,40.35 25.9,38.25 v1(26.45,37.7) ; v1(24.2,45.45) 24.2,45.2 25.25,44.15 U1.60 ; R50.1 7.4,30.7 5.2,32.9 v1(5.2,40)
  TOP w0.4: R50.1 10.59,27.98 S2.1
  BOTTOM w0.175: v1(5.2,40) 5.2,42.2 5.6,42.6 5.6,44.8 7.9,47.1 23.9,47.1 24.2,46.8 v1(24.2,45.45) 24.2,44.15 25.9,42.45 25.9,38.25 v1(26.45,37.7)
EECK: length 24.2
  TOP w0.175: U3.1 25.35,64.25 26,63.6 v1(28.3,63.6)
  TOP w0.2: R9.2 25.35,50.73 U4.2 v1(29.65,50.73)
  BOTTOM w0.175: v1(29.65,50.73) 29.87,50.73 30.6,51.47 30.6,54.9 29.5,56 29.5,61.2 28.3,62.4 v1(28.3,63.6)
EECS: length 25.3
  TOP w0.2: U4.1 25.12,52.01 R10.2 v1(29.66,52) ; U3.48 v1(24.14,65.78)
  BOTTOM w0.175: v1(29.66,52) 30.1,52.44 30.1,54.8 29.1,55.8 29.1,61 27.5,62.6 27.5,64 25.73,65.78 v1(24.14,65.78)
EEDA: length 28.1
  TOP w0.175: v1(29.2,62.8) 26.1,62.8 25.15,63.75 U3.2
  TOP w0.2: v1(30.7,50.3) 29.87,49.47 U4.3 25.58,49.47 R8.2 23.61,47.5 R11.1
  BOTTOM w0.175: v1(30.7,50.3) 31.1,50.7 31.1,55 29.9,56.2 29.9,62.1 v1(29.2,62.8)
JT_SRSTN: length 40
  TOP w0.175: v1(12.85,56.1) 13.45,55.5 14.4,55.5 14.8,55.1 U6.11 ; v1(7.6,55.9) 5.8,54.1 5.8,50.7 6.9,49.6 6.9,44.81 R42.1 ; U3.16 26.35,58.15 25.9,58.6 24.4,58.6 23.8,58 v1(23.2,58)
  BOTTOM w0.175: v1(23.2,58) 22.5,58 20.4,55.9 18.6,55.9 18.3,55.6 13.35,55.6 v1(12.85,56.1) 12.8,56.05 12.75,56.05 12.3,55.6 7.9,55.6 v1(7.6,55.9)
NRST: length 91.4
  TOP w0.175: R49.2 25.2,19.31 v1(25.2,20.1) 25.2,22.1 28.5,25.4 34.1,25.4 35.9,27.2 C48.1 ; v1(12.1,24.3) 11.5,23.7 8.8,23.7 4,28.5 J4.10 ; U2.7 23.45,36.75 24.25,35.95 25.3,35.95 v1(25.7,36.35) ; v1(16.15,38.5) 16.4,38.25 v2(18.5,38.25) 19.05,38.25 19.55,37.75 U1.7
  TOP w0.2: R42.2 v1(8.7,40.5) ; C48.1 S1.1
  BOTTOM w0.175: v1(25.7,36.35) 25.3,35.95 22.45,35.95 20.15,38.25 v2(18.5,38.25) 17.15,38.25 15.5,36.6 8.5,36.6 5.6,33.7 5.6,32.4 5.2,32 5.2,30.2 4,29 J4.10 ; v1(25.2,20.1) 24.8,20.5 21.1,20.5 20.4,21.2 16.2,21.2 13.1,24.3 v1(12.1,24.3)
  BOTTOM w0.2: v1(8.7,40.5) 9.9,39.3 15.3,39.3 16.1,38.5 v1(16.15,38.5)
OSC32_IN: length 20.8
  TOP w0.175: v1(23.9,39.05) 23.6,38.75 U2.3 ; v2(18.45,41.25) 18.75,41.25 20.25,39.75 U1.3
  TOP w0.2: v2(18.45,41.25) 17.15,41.25 16.4,42 16.4,47 Y2.1 C4.1
  BOTTOM w0.175: v2(18.45,41.25) 19.8,41.25 22,39.05 v1(23.9,39.05)
OSC32_OUT: length 26.3
  TOP w0.175: v1(24.45,38.11) 23.84,38.11 23.7,38.25 U2.4 ; v2(17.45,40.5) 18.85,40.5 20.1,39.25 U1.4
  TOP w0.2: C3.1 Y2.2 12.1,46 13,45.1 14.9,45.1 15.9,44.1 15.9,41.8 17.2,40.5 v2(17.45,40.5)
  BOTTOM w0.175: v2(17.45,40.5) 19.9,40.5 22.3,38.1 24.44,38.1 v1(24.45,38.11)
OSC_IN: length 23.2
  TOP w0.175: U1.5 19.95,38.75 18.92,39.78 v2(18.5,39.78) ; U2.5 23.7,37.75 24.05,37.4 v1(25.4,37.4)
  TOP w0.2: v2(18.5,39.78) 16.92,39.78 14.49,42.21 Y1.2
  TOP w0.4: C1.1 14.45,43 Y1.2
  BOTTOM w0.175: v2(18.5,39.78) 19.97,39.78 22.35,37.4 v1(25.4,37.4)
OSC_OUT: length 21.3
  TOP w0.175: v1(24.55,36.69) 24.16,36.69 23.6,37.25 U2.6 ; U1.6 19.7,38.25 18.96,38.99 v2(17.46,38.99)
  TOP w0.2: v2(17.46,38.99) 17.15,39.3 15.8,39.3 14.49,37.99 Y1.1
  TOP w0.4: C2.1 11.04,37.96 Y1.1
  BOTTOM w0.175: v1(24.55,36.69) 22.41,36.69 20.11,38.99 v2(17.46,38.99)
PA0: length 47
  TOP w0.175: v1(24.2,33.85) 24.2,34.3 23.25,35.25 U2.10 ; v2(17.5,33) 18.95,33 20.2,34.25 U1.14
  BOTTOM w0.175: J4.3 4,11.1 5.2,12.3 5.2,14.2 5.6,14.6 5.6,16.7 6,17.1 6,18.9 6.4,19.3 6.4,21.3 7.2,22.1 7.2,26.2 7.6,26.6 7.6,28.4 8,28.8 8,30.6 8.4,31 8.4,32.3 9.9,33.8 16.2,33.8 17,33 v2(17.5,33) 19.6,33 20.45,33.85 v1(24.2,33.85)
PA1: length 67.1
  TOP w0.175: 19.7,31.8 21.43,31.8 23.45,33.82 23.45,34.45 23.15,34.75 U2.11 ; 19.7,31.8 18.95,31.8 v1(18.5,32.25) ; 19.7,31.8 19.7,33.15 20.3,33.75 U1.15
  TOP w0.2: v1(18.4,7.3) 17.45,8.25 J4.2 ; R33.1 v1(21.3,7.3)
  BOTTOM w0.175: v1(18.5,32.25) 17.15,32.25 16,33.4 10.1,33.4 8.8,32.1 8.8,30.8 8.4,30.4 8.4,28.6 8,28.2 8,26.4 7.6,26 7.6,21.9 6.8,21.1 6.8,19.1 6.4,18.7 6.4,16.9 6,16.5 6,14.4 5.6,14 5.6,12.1 5.2,11.7 5.2,10 4,8.8 J4.2
  BOTTOM w0.2: v1(21.3,7.3) v1(18.4,7.3)
PA2: length 44.5
  TOP w0.3: v1(21.02,32.54) U1.16 21.87,33.25 22.52,33.91 U2.12
  BOTTOM w0.175: v1(21.02,32.54) 20.94,32.54 19.9,31.5 17.3,31.5 15.8,33 10.3,33 9.2,31.9 9.2,30.6 8.8,30.2 8.8,28.4 8.4,28 8.4,26.2 8,25.8 8,21.7 7.2,20.9 7.2,18.9 6.8,18.5 6.8,16.7 6.4,16.3 6.4,14.2 6,13.8 6,11.9 5.6,11.5 5.6,9.8 5.2,9.4 5.2,6.9 4.01,5.71 J4.1
PA3: length 2.2
  TOP w0.175: U1.17 23.25,32.09 23.68,32.52 U2.13
PA4: length 47.3
  TOP w0.175: 24.75,32.73 U2.14 U1.20 24.75,30.05 23.4,28.7 v1(23.4,26.2)
  TOP w0.2: R32.2 v1(39,23.1)
  BOTTOM w0.175: J3.1 46.4,6.31 46.39,6.31 45.7,7 45.7,9.5 45.4,9.8 45.4,11.8 45,12.2 45,14.1 44.6,14.5 44.6,16.3 44.2,16.7 44.2,18.6 43.7,19.1 43.7,20.9 41.5,23.1 v1(39,23.1) 38.2,23.1 37.6,22.5 27.1,22.5 v1(23.4,26.2)
PA5: length 45
  TOP w0.175: 25.25,32.73 U2.15 U1.21 25.25,29.95 24.2,28.9 v1(24.2,27.05)
  TOP w0.2: R31.2 v1(33,23.4)
  BOTTOM w0.175: v1(24.2,27.05) 24.2,26.3 27.5,23 30.8,23 31.2,23.4 v1(33,23.4) 34.6,23.4 35,23 37.4,23 38.3,23.9 41.3,23.9 44.1,21.1 44.1,19.3 44.6,18.8 44.6,16.9 45,16.5 45,14.7 45.4,14.3 45.4,12.4 45.8,12 45.8,10 46.9,8.9 46.9,8.35 J3.2
PA6: length 42.1
  TOP w0.175: v1(25,27.9) 25,29.1 25.75,29.85 U1.22 U2.16 25.75,32.73
  TOP w0.2: R29.2 v1(30,23.8)
  BOTTOM w0.175: J3.3 46.2,11.59 46.2,12.2 45.8,12.6 45.8,14.5 45.4,14.9 45.4,16.7 45,17.1 45,19 44.5,19.5 44.5,21.3 41.5,24.3 38,24.3 37.2,23.5 35.2,23.5 34.5,24.2 30.4,24.2 v1(30,23.8) 29.98,23.77 27.73,23.77 25,26.5 v1(25,27.9)
PA7: length 39
  TOP w0.175: 26.25,32.73 U2.17 U1.23 26.25,29.65 25.75,29.15 v1(25.75,28.75)
  TOP w0.2: v1(36.5,24.3) 36,23.8 R30.2
  BOTTOM w0.175: J3.4 46.2,14.13 46.2,14.7 45.8,15.1 45.8,16.9 45.4,17.3 45.4,19.2 44.9,19.7 44.9,21.5 41.7,24.7 37.7,24.7 37.3,24.3 v1(36.5,24.3) 35.1,24.3 34.7,24.7 27.8,24.7 25.75,26.75 v1(25.75,28.75)
PA8: length 85.1
  TOP w0.175: U1.41 34.7,37.25 34.95,37.5 v1(36.15,37.5) 36.9,38.25 36.9,40.2 v1(38.7,42) ; v1(28.05,36.01) 28.06,36.01 28.3,36.25 U2.29
  TOP w0.2: Q2.1 v1(33.75,67.35) ; R47.2 44.29,49.59 45.2,50.5 45.2,52.17 J3.20
  BOTTOM w0.175: J3.20 47,53.6 45.8,52.4 45.8,50.5 45.4,50.1 45.4,48.3 45,47.9 45,46 44.6,45.6 44.6,43.4 44.2,43 44.2,41 43.8,40.6 43.8,39.1 42.2,37.5 v1(36.15,37.5) 34.55,37.5 33.35,36.3 28.34,36.3 v1(28.05,36.01) ; v1(38.7,42) 39.2,42 41.8,44.6 41.8,58.1 39.5,60.4 39.5,66.5 38.65,67.35 v1(33.75,67.35)
PA9: length 60.8
  TOP w0.175: J3.21 48.34,57.85 48.34,59.76 47.8,60.3 40.2,60.3 37.41,63.09 R59.2 ; v1(27.15,36.75) U2.30 ; v1(35.25,38.25) 35.1,38.25 34.6,37.75 U1.42
  BOTTOM w0.175: v1(27.15,36.75) 33.15,36.75 34.65,38.25 v1(35.25,38.25) 42.35,38.25 43.4,39.3 43.4,40.8 43.8,41.2 43.8,43.2 44.2,43.6 44.2,45.8 44.6,46.2 44.6,48.1 45,48.5 45,50.3 45.4,50.7 45.4,52.6 45.8,53 45.8,54.6 46.2,55 46.2,55.71 J3.21
PA10: length 57
  TOP w0.175: R34.2 34.11,63.09 34.8,62.4 37.4,62.4 40.75,59.05 J3.22 ; U1.43 34.2,38.25 34.95,39 v1(36.15,39) ; U2.31 29.3,37.25 29.05,37.5 v1(28.95,37.5)
  BOTTOM w0.175: v1(28.95,37.5) 29.15,37.3 33.05,37.3 34.75,39 v1(36.15,39) 42.5,39 43,39.5 43,41 43.4,41.4 43.4,43.4 43.8,43.8 43.8,46 44.2,46.4 44.2,48.3 44.6,48.7 44.6,50.5 45,50.9 45,52.8 45.4,53.2 45.4,54.8 45.8,55.2 45.8,57.1 47,58.3 J3.22
PA11: length 54.3
  TOP w0.175: U1.44 34.1,38.75 35.1,39.75 v1(35.25,39.75) ; U2.32 30.25,37.75 v1(29.95,38.05)
  TOP w0.2: U11.6 v1(42.75,62.56)
  BOTTOM w0.175: J3.23 45.89,62.7 44.23,62.7 43.43,63.5 42.5,63.5 41.8,62.8 41.8,62.6 42,62.4 42.59,62.4 v1(42.75,62.56) 42.75,61.95 42,61.2 42,60.37 44.46,57.9 44.46,51.4 43.28,50.21 43.28,44.06 38.97,39.75 v1(35.25,39.75) 31.7,39.75 31.55,39.6 31.55,39.4 31.73,39.23 32.92,39.23 33.05,39.1 33.05,38.9 32.9,38.75 30.7,38.75 30.55,38.6 30.55,38.4 30.68,38.27 31.12,38.27 31.25,38.15 31.25,37.9 31.1,37.75 30.25,37.75 v1(29.95,38.05)
PA12: length 58.8
  TOP w0.175: v1(36.15,40.46) 34.96,40.46 33.75,39.25 U1.45
  TOP w0.2: v1(40.85,62.56) U11.4 40.85,64.05 40.1,64.8 40.1,65.4 39.11,66.39 R46.2 ; v1(27.7,37.9) 28.07,38.27 29.15,38.27 29.65,38.77 30.28,38.77 30.8,38.25 U2.33
  BOTTOM w0.175: v1(27.7,37.9) 28.05,38.25 29.1,38.25 29.65,38.8 30.15,38.8 31.5,40.15 34.5,40.15 34.81,40.46 v1(36.15,40.46) 36.49,40.8 36.92,40.8 37.12,40.6 37.12,40.38 37.3,40.2 38.81,40.2 42.88,44.26 42.88,50.38 44.06,51.56 44.06,57.74 41.6,60.2 41.6,61.2 40.85,61.95 v1(40.85,62.56) 40.86,62.56 42.2,63.9 43.7,63.9 44.4,63.2 46.07,63.2 J3.24
PA13: length 49.5
  TOP w0.175: U1.46 33.65,39.75 35.1,41.2 v1(35.25,41.2) ; v1(29.8,39.55) 30.05,39.55 30.85,38.75 U2.34
  TOP w0.2: R36.2 v1(42.7,53.4)
  BOTTOM w0.175: v1(29.8,39.55) 30.9,40.65 33.4,40.65 33.95,41.2 v1(35.25,41.2) 39.1,41.2 42.2,44.3 42.2,50.5 42.7,51 v1(42.7,53.4) 42.7,57.9 40,60.6 40,64.2 41.2,65.4 43.2,65.4 44.47,66.67 J3.25
PA14: length 60.9
  TOP w0.175: U1.49 30.75,41.91 30.32,41.48 U2.37 ; R38.2 36.7,53 37.1,52.6 v1(37.1,48.4)
  TOP w0.2: v1(31.46,43.8) 31,43.8 30.75,43.55 U1.49
  BOTTOM w0.175: v1(31.46,43.8) 31.46,44.6 ; 31.46,44.6 32.7,44.6 33.4,45.3 33.4,46.66 34.54,47.8 36.5,47.8 v1(37.1,48.4) ; 31.46,44.6 31.46,45.66 31.8,46 31.8,46.9 31.5,47.2 31,47.2 29.4,48.8 28.7,48.8 26.4,51.1 8.6,51.1 6.4,53.3 6.4,57.3 5.6,58.1 5.6,60.2 5.2,60.6 5.2,62.4 4,63.6 J4.24
PA15: length 65.9
  TOP w0.175: v1(35.9,48.8) 35.9,51.6 33.7,53.8 R37.2 ; U1.50 30.25,43.75 31.9,45.4 v1(32.3,45.4) 32.3,42.6 30.25,40.55 29.59,40.55 29.25,40.89 U2.38
  BOTTOM w0.175: v1(35.9,48.8) 35.5,48.4 33.6,48.4 32.3,47.1 ; 32.3,47.1 31.7,47.7 31.1,47.7 29.6,49.2 28.9,49.2 26.6,51.5 8.8,51.5 6.8,53.5 6.8,56.1 6.79,56.11 6.79,56.69 6.8,56.7 6.8,57.5 6,58.3 6,60.4 5.6,60.8 5.6,62.6 5.2,63 5.2,65.1 4,66.3 J4.25 ; 32.3,47.1 v1(32.3,45.4)
PB0: length 55.1
  TOP w0.175: U1.26 27.75,29.65 28,29.4 v1(28,27.85)
  TOP w0.2: v1(14.6,24.8) 12.7,22.9 11.4,22.9 10.11,21.61 R64.1 ; v1(26.36,33.9) 26.75,33.52 U2.18
  BOTTOM w0.175: 28,29.6 v1(28,27.85) 28,27.3 29.4,25.9 42.3,25.9 46.1,22.1 46.1,21.85 J3.7 ; 28,29.6 28,30.15 26.36,31.79 v1(26.36,33.9) ; 28,29.6 25.4,29.6 22.5,26.7 16.5,26.7 v1(14.6,24.8)
PB1: length 42.1
  TOP w0.175: v1(26.1,34.95) 26.4,34.95 27.25,34.1 U2.19 ; J3.8 45.09,23.49 43.9,22.3 D3.C ; U1.27 28.25,29.8 28.75,29.3 v1(28.75,28.75)
  BOTTOM w0.175: v1(26.1,34.95) 26.45,34.95 27.2,34.2 27.2,31.7 28.75,30.15 v1(28.75,28.75) 28.75,27.35 29.8,26.3 42.5,26.3 45.31,23.49 J3.8
PB2: length 63.2
  TOP w0.175: U2.20 27.75,34.19 27,34.94 v1(27,35.6) ; U1.28 28.75,30 29.5,29.25 v1(29.5,27.85) 28.55,26.9 27.8,26.9 25.7,24.8 25.1,24.8 v1(24.3,24)
  TOP w0.3: R51.1 10.7,32.3 11.4,31.6 11.4,29.6 12,29 12,26.83 S2.2
  BOTTOM w0.175: v1(27,35.6) 27,34.94 27.19,34.75 27.2,34.75 27.75,34.2 27.75,31.95 29.5,30.2 v1(29.5,27.85) 29.5,27.7 30.5,26.7 42.7,26.7 43.37,26.03 J3.9 ; S2.2 12.77,25.43 14.21,23.99 14.79,23.99 14.8,24 v1(24.3,24)
PB3: length 55.4
  TOP w0.175: U1.55 27.75,44.75 28,45 v1(28,46.35) 28.95,47.3 37.4,47.3 38.1,48 38.1,52.79 R35.2
  TOP w0.2: v1(28.9,40.17) 28.75,40.33 U2.39
  BOTTOM w0.175: J4.19 5.27,51.43 7.6,49.1 25.4,49.1 28,46.5 v1(28,46.35) 28,44.6 28.9,43.7 v1(28.9,40.17)
PB4: length 39.8
  TOP w0.175: v1(28.85,39.05) 28.15,39.75 28.15,40.5 28.25,40.6 U2.40 ; U1.56 v1(27.25,45.45)
  TOP w0.2: J4.18 4.01,48.9 R41.2
  BOTTOM w0.175: v1(28.85,39.05) 28.19,39.71 28.19,43.71 27.25,44.65 v1(27.25,45.45) 27.25,46.65 25.2,48.7 4.19,48.7 J4.18
PB5: length 37.9
  TOP w0.175: v1(26.45,46.35) 26.45,45.15 26.75,44.85 U1.57 ; U2.41 v1(27.75,39.1)
  BOTTOM w0.175: v1(27.75,39.1) 27.75,43.3 26.45,44.6 v1(26.45,46.35) 26.45,46.65 24.8,48.3 7.3,48.3 5.35,46.35 J4.17
PB6: length 36
  TOP w0.175: v1(25.7,45.45) 25.7,45.25 26.25,44.7 U1.58 ; v1(27,39.9) 27.25,40.15 U2.42
  BOTTOM w0.175: v1(27,39.9) 27,43.15 25.7,44.45 v1(25.7,45.45) 25.7,46.7 24.5,47.9 7.5,47.9 4,44.4 J4.16
PB7: length 40.8
  TOP w0.175: v1(24.95,46.35) 24.95,45.15 25.75,44.35 U1.59 ; U2.43 26.75,40.65 26.25,40.15 26.25,39.25 v1(26.7,38.8)
  BOTTOM w0.175: v1(26.7,38.8) 26.25,39.25 26.25,43 24.95,44.3 v1(24.95,46.35) 24.95,46.75 24.2,47.5 7.7,47.5 5.2,45 5.2,42.8 4,41.6 J4.15
PB8: length 40.8
  TOP w0.175: v1(25.19,38.95) 25.4,39.16 25.4,40.4 25.75,40.75 U2.45 ; U1.61 24.75,43.85 23.45,45.15 v1(23.45,46.35)
  BOTTOM w0.175: J4.14 4.07,38.8 5.3,38.8 6,39.5 6,44.6 8.1,46.7 23.1,46.7 v1(23.45,46.35) 23.45,44.1 25.4,42.15 25.4,39.16 v1(25.19,38.95)
PB9: length 38
  TOP w0.175: v1(24.6,39.85) 24.6,40.2 25.25,40.85 U2.46 ; U1.62 24.25,43.75 22.7,45.3 v1(22.7,45.45)
  BOTTOM w0.175: v1(24.6,39.85) 24.6,42.15 22.7,44.05 v1(22.7,45.45) 21.85,46.3 8.3,46.3 6.4,44.4 6.4,39.1 4,36.7 J4.13
PB10: length 28.9
  TOP w0.175: U1.29 29.25,30.05 30.25,29.05 v1(30.25,28.75) ; U2.21 28.25,33.66 v1(28.55,33.96)
  BOTTOM w0.175: J3.10 46.97,28.57 45.5,27.1 30.7,27.1 30.25,27.55 v1(30.25,28.75) 30.25,30.15 28.55,31.85 v1(28.55,33.96)
PB11: length 32.5
  TOP w0.175: v1(29.8,34.2) 28.75,33.15 U2.22 ; U1.30 29.75,30.35 31,29.1 v1(31,27.85)
  BOTTOM w0.175: J3.11 46.31,31.8 37.4,31.8 36.6,31 33.3,31 32,32.3 32,33.5 31.3,34.2 v1(29.8,34.2) 29.8,31.35 31,30.15 v1(31,27.85)
PB12: length 63.4
  TOP w0.175: v1(42.3,19) 42.4,19 43.5,20.1 43.5,22.5 45.5,24.5 45.5,32.2 46.95,33.65 J3.12
  TOP w0.2: R61.1 v1(16.1,22.4)
  TOP w0.3: U2.25 31.48,33.83 32.05,33.25 U1.33 v1(32.98,32.54)
  BOTTOM w0.175: v1(32.98,32.54) 32.98,32.52 34.1,31.4 36.4,31.4 37.2,32.2 41.7,32.2 43.15,33.65 J3.12 ; v1(42.3,19) 41.1,19 39.2,20.9 21.5,20.9 20.8,21.6 16.9,21.6 v1(16.1,22.4)
PB13: length 67.1
  TOP w0.175: U1.34 33.65,33.75 34.15,33.25 34.15,31.8 ; 34.15,31.8 34.9,31.8 v1(35.35,32.25) ; 34.15,31.8 32.5,31.8 30.51,33.79 30.51,34.49 30.76,34.75 U2.26 ; v1(41.5,19.8) 42.6,19.8 43.1,20.3 43.1,22.4 42.5,23 42.5,33.1 45.59,36.19 J3.13
  TOP w0.2: R66.2 v1(20.6,22.4)
  BOTTOM w0.175: v1(20.6,22.4) 21.7,21.3 39.4,21.3 40.9,19.8 v1(41.5,19.8) ; J3.13 45.09,36.19 41.5,32.6 37,32.6 36.65,32.25 v1(35.35,32.25)
PB14: length 75.4
  TOP w0.175: J3.14 46.93,38.73 41.7,33.5 v1(41.7,21.6) ; U1.35 33.75,34.25 35,33 v1(36.2,33) ; v1(28.05,34.95) 28.33,34.67 29.27,34.67 29.85,35.25 U2.27
  TOP w0.2: R67.2 v1(17.6,22.4)
  BOTTOM w0.175: J3.14 47,38.7 41.3,33 v1(36.2,33) 34.8,33 32.85,34.95 29.5,34.95 29.3,34.75 28.25,34.75 v1(28.05,34.95) ; v1(41.7,21.6) 40.3,21.6 39.8,22.1 22.7,22.1 21.2,23.6 18.8,23.6 v1(17.6,22.4)
PB15: length 78.5
  TOP w0.175: v1(42.3,20.6) 42.5,20.8 42.5,22.4 42.1,22.8 42.1,33.3 46.3,37.5 47.7,37.5 48.3,38.1 48.3,39.97 J3.15 ; v1(35.35,33.75) 35.15,33.75 34.15,34.75 U1.36 ; v1(29.05,35.5) 29.3,35.75 U2.28
  TOP w0.2: R65.1 v1(19.1,22.4)
  BOTTOM w0.175: v1(29.05,35.5) 33.6,35.5 v1(35.35,33.75) 41.45,33.75 45.8,38.1 45.8,39.6 47,40.8 J3.15 ; v1(42.3,20.6) 40.7,20.6 39.6,21.7 22.5,21.7 21,23.2 19.9,23.2 v1(19.1,22.4)
PC0: length 25.1
  TOP w0.175: U1.8 19.3,37.25 19.05,37.5 v2(17.5,37.5)
  BOTTOM w0.175: J4.9 4,26.6 5.2,27.8 5.2,29.6 5.6,30 5.6,31.8 6,32.2 6,33.5 8.7,36.2 15.7,36.2 17,37.5 v2(17.5,37.5)
PC1: length 26.9
  TOP w0.175: U1.9 v2(18.5,36.75)
  BOTTOM w0.175: J4.8 4.8,24.29 4.8,24.3 5.2,24.7 5.2,27.2 5.6,27.6 5.6,29.4 6,29.8 6,31.6 6.4,32 6.4,33.3 8.9,35.8 15.9,35.8 16.85,36.75 v2(18.5,36.75)
PC2: length 28.8
  TOP w0.175: U1.10 19.3,36.25 19.05,36 v2(17.5,36)
  BOTTOM w0.175: J4.7 4,21.3 5.6,22.9 5.6,27 6,27.4 6,29.2 6.4,29.6 6.4,31.4 6.8,31.8 6.8,33.1 9.1,35.4 16.1,35.4 16.7,36 v2(17.5,36)
PC3: length 30.8
  TOP w0.175: v2(18.5,35.25) 19.15,35.25 19.65,35.75 U1.11
  BOTTOM w0.175: J4.6 4,18.7 5.2,19.9 5.2,21.9 6,22.7 6,26.8 6.4,27.2 6.4,29 6.8,29.4 6.8,31.2 7.2,31.6 7.2,32.9 9.27,34.98 16.3,34.98 16.57,35.25 v2(18.5,35.25)
PC4: length 31.7
  TOP w0.175: v1(26.5,27.9) 26.5,29.15 26.75,29.4 U1.24
  BOTTOM w0.175: J3.5 46.2,16.67 46.2,17.1 45.8,17.5 45.8,19.4 45.3,19.9 45.3,21.7 41.9,25.1 28.3,25.1 26.5,26.9 v1(26.5,27.9)
PC5: length 28.5
  TOP w0.175: U1.25 v1(27.25,28.75)
  BOTTOM w0.175: v1(27.25,28.75) 27.25,27.15 28.9,25.5 42.1,25.5 45.7,21.9 45.7,20.1 46.2,19.6 46.2,19.21 J3.6
PC6: length 20.5
  TOP w0.175: v1(36.2,34.5) 35,34.5 34.25,35.25 U1.37
  BOTTOM w0.175: J3.16 46.2,43.01 46.2,42.6 45.8,42.2 45.8,40.2 45.4,39.8 45.4,38.3 41.6,34.5 v1(36.2,34.5)
PC7: length 22.3
  TOP w0.175: v1(35.35,35.25) 34.9,35.25 34.4,35.75 U1.38
  BOTTOM w0.175: v1(35.35,35.25) 41.75,35.25 45,38.5 45,40 45.4,40.4 45.4,42.4 45.8,42.8 45.8,44.9 47,46.1 J3.17
PC8: length 57.7
  TOP w0.175: U1.39 34.65,36.25 34.9,36 v1(36.15,36) 36.4,36 37.8,37.4 37.8,39.9 38.2,40.3 38.9,40.3 39.3,39.9 39.3,27.6 39,27.3 36.6,27.3 34.3,25 28.9,25 27,23.1 R23.1
  BOTTOM w0.175: v1(36.15,36) 41.9,36 44.6,38.7 44.6,40.2 45,40.6 45,42.6 45.4,43 45.4,45.2 45.8,45.6 45.8,47.5 47,48.7 J3.18
PC9: length 60.3
  TOP w0.175: R27.1 28.5,23.8 29.3,24.6 34.5,24.6 36.8,26.9 39.2,26.9 39.7,27.4 39.7,40.1 39.1,40.7 38,40.7 37.4,40.1 37.4,37.6 36.55,36.75 v1(35.3,36.75) U1.40
  BOTTOM w0.175: J3.19 47,51.1 45.8,49.9 45.8,48.1 45.4,47.7 45.4,45.8 45,45.4 45,43.2 44.6,42.8 44.6,40.8 44.2,40.4 44.2,38.9 42.05,36.75 v1(35.3,36.75)
PC10: length 75
  TOP w0.175: R28.1 40.5,25.8 41.3,26.6 41.3,44.5 38.98,46.82 31.52,46.82 v1(31.05,46.35) 31.05,45.2 29.75,43.9 U1.51
  BOTTOM w0.175: v1(31.05,46.35) 31.05,46.55 29.2,48.4 28.5,48.4 26.2,50.7 8.4,50.7 6,53.1 6,57.1 5.2,57.9 5.2,60 4,61.2 J4.23
PC11: length 77.5
  TOP w0.175: R26.1 37.5,25 38.2,25.7 39.8,25.7 40.9,26.8 40.9,44.3 38.9,46.3 34.6,46.3 v1(34.3,46) ; v1(30.25,45.45) 30.25,45.15 29.25,44.15 U1.52
  BOTTOM w0.175: J4.22 4,58.5 5.6,56.9 5.6,52.9 8.2,50.3 26,50.3 28.3,48 29,48 30.25,46.75 v1(30.25,45.45) 30.25,43.85 31.1,43 31.8,43 34.3,45.5 v1(34.3,46)
PC12: length 79.4
  TOP w0.175: v1(29.5,46.35) 29.5,45.1 28.75,44.35 U1.53 ; v1(37.9,44.8) 38.3,45.2 38.8,45.2 40.1,43.9 40.1,27.2 39.4,26.5 37,26.5 34.7,24.2 32.3,24.2 31.5,23.4 R25.1
  BOTTOM w0.175: v1(37.9,44.8) 36.5,46.2 35.7,46.2 32.1,42.6 30.9,42.6 29.8,43.7 29.8,44.4 29.5,44.7 v1(29.5,46.35) 29.5,46.9 28.8,47.6 28.1,47.6 25.8,49.9 8,49.9 5.2,52.7 5.2,54.8 4,56 J4.21
PC13: length 39
  TOP w0.175: 19.8,42.2 v1(17.4,42.2) ; 19.8,42.2 21.55,42.2 23.43,40.33 23.43,39.58 23.1,39.25 U2.2 ; 19.8,42.2 19.8,40.8 20.35,40.25 U1.2
  BOTTOM w0.175: v1(17.4,42.2) 17.4,44.1 16,45.5 8.7,45.5 7.2,44 7.2,38.7 5.6,37.1 5.6,35.1 5.2,34.7 5.2,32.6 4,31.4 J4.11
PD2: length 73.8
  TOP w0.175: v1(28.75,45.45) 28.75,45.1 28.25,44.6 U1.54 ; R24.1 34.5,23.4 37.2,26.1 39.6,26.1 40.5,27 40.5,44.1 38.8,45.8 36.5,45.8 v1(36.1,45.4)
  BOTTOM w0.175: v1(36.1,45.4) 35.6,45.4 32.4,42.2 30.7,42.2 29.4,43.5 29.4,44 28.75,44.65 v1(28.75,45.45) 28.75,46.85 28.4,47.2 27.9,47.2 25.6,49.5 7.8,49.5 4,53.3 J4.20
RXD: length 8.4
  TOP w0.175: U3.39 29.35,66.65 29.6,66.9 30.6,66.9 32.3,65.2 33,65.2 33.5,65.7 34.51,65.7 R59.1
SRST: length 10.7
  TOP w0.175: U3.11 22.35,59.25 21.5,58.4 18.5,58.4 17.5,57.4 17.5,55 16.95,54.45 U6.12
SRST_OE: length 15.2
  TOP w0.175: R39.2 20,51.4 17.9,53.5 17.9,57.2 18.7,58 21.7,58 22.45,58.75 U3.12
  TOP w0.2: U6.13 17.9,53.8
TRST: length 3.8
  TOP w0.175: 21.62,55.75 22.35,55.75 23.5,56.9 24.1,56.9 24.43,57.23 U3.13
TRST_OE: length 20.7
  TOP w0.175: U3.15 25.85,57.95 25.6,58.2 24.6,58.2 23.7,57.3 22.8,57.3 22.5,57.6 18.9,57.6 18.3,57 18.3,53.8 20.2,51.9 21,51.9 21.5,51.4 R40.2
  TOP w0.2: 18.3,54.5 20,54.5 20.6,55.1 21.62,55.1
TXD: length 6.1
  TOP w0.175: R34.1 29.09,64.71 28.85,64.95 U3.40
USB_CLK: length 8.4
  TOP w0.175: R38.1 36.59,56.01 35.38,57.23 U3.24
  TOP w0.3: R38.1 R58.2
USB_TDI: length 6.3
  TOP w0.175: R37.1 30.29,56.01 29.85,56.45 U3.23
  TOP w0.3: R37.1 R57.2
USB_TDO: length 13.8
  TOP w0.175: R35.1 39.69,56.01 37.9,57.8 31,57.8 30.4,58.4 29.7,58.4 29.35,58.05 U3.22
  TOP w0.3: R35.1 R55.2
USB_TMS: length 17.8
  TOP w0.175: R36.1 42.59,56.01 40.4,58.2 31.2,58.2 30.6,58.8 29.4,58.8 28.85,58.25 U3.21
  TOP w0.3: R36.1 R56.2
N50123: length 25.6
  TOP w0.175: U3.7 22.35,61.25 22,60.9 22,60.4 21.7,60.1 20.6,60.1 20.3,60.4 20.3,61.5 19.49,62.31 R13.1
  TOP w0.2: U12.4 v1(12.45,63.25) ; U3.7 25.15,61.25 v1(25.5,61.6)
  BOTTOM w0.2: v1(25.5,61.6) 24.1,61.6 23.73,61.23 20.37,61.23 16.7,64.9 13.5,64.9 13,64.4 13,63.8 v1(12.45,63.25)
N50127: length 3.8
  TOP w0.2: R4.2 23.76,67.8 C18.1 25.85,67.2 U3.46
N50535: length 1.9
  TOP w0.2: U3.20 28.35,55.56 R7.1
N50793: length 11.1
  TOP w0.2: U3.43 27.35,72.5 Y3.1
  TOP w0.4: Y3.1 27.9,73.05 C20.1
N50801: length 13.5
  TOP w0.2: Y3.2 24.46,73.04 26.85,70.65 U3.44
  TOP w0.4: C21.1 22.8,73.05 Y3.2
N51029: length 8.2
  TOP w0.6: R5.1 18.8,65.5 18.3,66 ; D2.A L1.1 17.12,66 18.3,66 ; C10.1 20,68.6 18.3,66.9 18.3,66
N51243: length 3.3
  TOP w0.5: L1.2 15.62,67.97 15.1,68.5 J1.1
N51319: length 2.3
  TOP w0.2: U3.5 22.05,62.25 21.8,62.5 R13.2
N51343: length 18.8
  TOP w0.2: U12.6 v1(14.35,63.26) ; v1(25.5,60.3) 25.45,60.3 25,60.75 U3.8
  BOTTOM w0.2: v1(14.35,63.26) 14.14,63.26 13.5,63.9 13.5,64.2 13.8,64.5 16.5,64.5 20.17,60.83 23.67,60.83 24.2,60.3 v1(25.5,60.3)
N51347: length 4.3
  TOP w0.175: R6.1 21.11,63.89 22.25,62.75 U3.4
  TOP w0.2: R5.2 R6.1
N51363: length 2.6
  TOP w0.2: C19.1 21.95,61.75 U3.6
N51511: length 3
  TOP w0.2: R11.2 25.81,48.2 U4.4
N51727: length 2
  TOP w0.6: D1.A R12.2
N70187: length 21.1
  TOP w0.2: U10.7 29.4,10 29.1,10.3 v1(27,10.3) R15.2 ; v1(27,18.7) R23.2 27.81,21.6 29.2,21.6 30,20.8 R29.1
  BOTTOM w0.2: v1(27,18.7) v1(27,10.3)
N70219: length 21.5
  TOP w0.2: v1(31.9,17.4) 31.9,19.2 31.5,19.6 R25.2 R31.1 ; U10.5 31.6,11.7 v1(31.5,11.8) R17.2
  BOTTOM w0.2: v1(31.9,17.4) 31.9,12.2 v1(31.5,11.8)
N70227: length 25.3
  TOP w0.2: R32.1 R26.2 v1(37.5,17.6) ; U10.2 v1(34.9,14.9) 34.8,14.8 R18.2
  BOTTOM w0.2: v1(34.9,14.9) 34.9,15 v1(37.5,17.6)
N70305: length 4
  TOP w0.2: R21.2 28.65,17.8 U10.S2
N70345: length 5.3
  TOP w0.4: R33.2 R22.1 25.21,5 ; 25.21,5 25.26,5.05 U10.G2 ; 25.21,5 25.21,4.31 C47.1
N70603: length 18.6
  TOP w0.175: R27.2 28.61,20.79 v1(30.9,18.5)
  TOP w0.2: U10.8 v1(28.3,8.8) R19.2
  BOTTOM w0.2: v1(28.3,8.8) 28.5,9 28.5,10.6 30.9,13 v1(30.9,18.5)
N14914218: length 24.7
  TOP w0.175: R24.2 34.39,20.79 32.8,19.2 v1(32.8,18.5)
  TOP w0.2: R16.2 v1(33.8,13.3) U10.3 ; R24.2 R30.1
  BOTTOM w0.2: v1(32.8,18.5) 32.8,15.6 33.8,14.6 v1(33.8,13.3)
N14919761: length 27
  TOP w0.175: R28.2 40.5,19.1 37.7,16.3 36,16.3
  TOP w0.2: U10.1 36,16.3 R20.2
N14928576: length 23.3
  TOP w0.175: v1(7.6,54.7) 6.3,53.4 6.3,51 7.71,49.59 R41.1 7.71,47.32 R54.2
  TOP w0.2: v1(19,55.2) 19.6,55.2 20.8,56.4 21.62,56.4
  BOTTOM w0.175: v1(19,55.2) 8.1,55.2 v1(7.6,54.7)
N14948550: length 7.1
  TOP w0.3: L2.2 43.88,69.67 42.9,68.7 38.9,68.7 38.6,69 J2.1
N14948554: length 8.1
  TOP w0.2: U11.1 42.75,67.35 42.3,67.8 41.1,67.8 40.8,68.1 38.2,68.1 37.8,68.5 J2.2
N14948558: length 8.3
  TOP w0.2: J2.3 37,68.5 37.9,67.6 40.6,67.6 40.88,67.32 40.88,67.08 40.7,66.9 40.22,66.9 39.98,66.66 39.98,66.38 40.16,66.2 40.55,66.2 U11.3
N14952468: length 2.3
  TOP w0.2: R46.1 37.49,66.3 38.64,65.15 Q1.2
N14953185: length 11.1
  TOP w0.2: Q1.1 38.92,63.77 36.4,66.3 35.41,66.3 R45.1 32.81,66.29 Q2.3 32.77,66.3 32.1,66.3 30.61,67.79 R44.2
N14959571: length 3.5
  TOP w0.2: J1.3 13.5,68.5 12.45,67.45 U12.3
N14961045: length 3.5
  TOP w0.2: U12.1 14.35,67.15 13.74,67.76 13.74,68.04 14.3,68.6 J1.2
N14964930: length 5.3
  TOP w0.175: U1.31 30.25,30.35 30.8,29.8 31.4,29.8 32.3,28.9 C27.1
  TOP w0.2: R43.1 32.79,28.89 C27.1
N14964937: length 5.2
  TOP w0.2: U1.47 33.55,40.25 34.2,40.9 34.2,41.8 C28.1 36.59,42.7 R48.1
N14983071: length 2.7
  TOP w0.4: S2.4 18.61,27.98 R52.2
N14983075: length 2.4
  TOP w0.4: R53.2 19.18,26.01 S2.3
N14990127: length 5.4
  TOP w0.175: U8.8 12.8,16.5 12.8,18.8 11.61,19.99 R62.2
N14990147: length 6
  TOP w0.175: U8.4 18.8,16.5 18.8,18.8 19.1,19.1 19.7,19.1 20.59,19.99 R66.1
N14990153: length 5.2
  TOP w0.175: U8.6 16.8,16.5 16.8,18.6 17.6,19.4 R67.1
N14990191: length 3
  TOP w0.175: R65.2 19.1,19.9 17.8,18.6 U8.3
N14990197: length 4.1
  TOP w0.2: U8.5 16.1,17.8 R61.2 R60.2
N14990201: length 6.5
  TOP w0.175: R64.2 10.19,19.99 11,20.8 12.29,20.8 R63.2
  TOP w0.2: U8.7 13.8,18.8 13.1,19.5 R63.2
N15001570: length 1.7
  TOP w0.6: D3.A R70.2

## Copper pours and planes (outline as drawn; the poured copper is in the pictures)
+3V3 on TOP: 23.3,55.3 23.3,55.9 23.9,56.5 24.4,56.5 24.7,56.2 27,56.2 27,55.3
+3V3 on TOP: 9.5,59.3 10.3,59.3 10.3,57.3 12.1,57.3 12.1,55.6 12.8,54.9 14,54.9 14.6,54.3 14.6,52.6 15.7,52.6 15.7,53.2 16.2,53.2 16.2,52.6 17.8,52.6 18.9,51.5 18.9,50.8 10.8,50.8 10.1,50.1 10.1,48.3 9.7,47.9 9.7,46.8 9,46.8 9,49.2 6.8,51.4 6.8,52.8 8.6,54.6 8.6,57.3 9.5,57.3
+3V3 on BOTTOM: 11.9,54.6 19.7,54.6 24.5,59.4 27,59.4 27.3,59.1 27.3,52.5 26.8,52 11.9,52
+5V on TOP: 6.7,61.9 6.7,57.8 9,57.8 9,61.9
+5V on TOP: 16.3,60.7 17.9,60.7 17.9,58.6 17.8,58.5 15.9,58.5 15.2,57.8 14.7,57.8 14.4,58.1 14.4,59.4 14.8,59.8 15.8,59.8 16.2,60.2 16.2,60.6
+5V on BOTTOM: 8,59.8 8,57.8 15.5,57.8 15.5,59.8
GND on TOP: 12.9,58.6 11.8,58.6 11.8,60 11,60 11,60.8 13.2,60.8 13.6,61.2 15.2,61.2 15.5,60.9 15.5,60.5 15.2,60.2 14.5,60.2
GND on TOP: 6.8,67.3 6.8,64.6 9,64.6 9,67.3
GND on TOP: 11.4,41.8 10.6,41.8 10.5,41.7 10.5,41.2 8.8,39.5 8.8,36.1 11.8,33.1 11.8,30.1 12.5,29.4 12.5,26.8 15.9,26.8 15.9,28.4 14.8,28.4 13.1,30.1 13.1,31.9 13.7,32.5 15,32.5 15.1,32.6 15.1,33.2 15,33.3 13.5,33.3 10,36.8 10,38.6 10.6,39.2 11.4,39.2 11.5,39.3 11.5,41.7
GND on TOP: 35.1,61.9 35.1,59.3 34.8,59 33.7,59 33.7,58.6 37,58.6 37,61.9
